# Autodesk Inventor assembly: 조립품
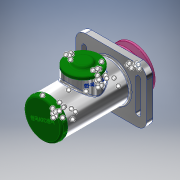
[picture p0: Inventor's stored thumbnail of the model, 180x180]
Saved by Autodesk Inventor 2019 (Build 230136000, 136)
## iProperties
Created: 2021-07
Part Number: 조립품
Material: 일반
Document SubType Name: Assembly
Designer: jun-2-10
Author: jun-2-10
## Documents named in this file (20)
- C:\Users\jun-2-10\Desktop\710706V1017\710706V1017\조립품.iam
- C:\Users\jun-2-10\Desktop\710706V1017\710706V1017\본체.ipt
- C:\Users\jun-2-10\Desktop\710706V1017\710706V1017\사이드 커버.ipt
- 사이드 커버.ipt
- C:\Users\jun-2-10\Desktop\710706V1017\710706V1017\축.ipt
- C:\Users\jun-2-10\Desktop\710706V1017\710706V1017\멈춤링 15 x 1.ipt
- C:\Users\jun-2-10\Desktop\710706V1017\710706V1017\멈춤링 35 x 1.6.ipt
- C:\Users\jun-2-10\Desktop\710706V1017\710706V1017\베어링 15 x 35 x 11.ipt
- C:\Users\jun-2-10\Desktop\710706V1017\710706V1017\부시1.ipt
- C:\Users\jun-2-10\Desktop\710706V1017\710706V1017\부시2.ipt
- C:\Users\jun-2-10\Desktop\710706V1017\710706V1017\와셔 10 x 21.ipt
- C:\Users\jun-2-10\Desktop\710706V1017\710706V1017\너트 M10.ipt
- C:\Users\jun-2-10\Desktop\710706V1017\710706V1017\키 4 x 4 x 18.ipt
- C:\Users\jun-2-10\Desktop\710706V1017\710706V1017\V-벨트풀리.ipt
- C:\Users\jun-2-10\Desktop\710706V1017\710706V1017\와셔 4 x 16.ipt
- C:\Users\jun-2-10\Desktop\710706V1017\710706V1017\볼트 M4 x 10.ipt
- C:\Users\jun-2-10\Desktop\710706V1017\710706V1017\오일 실 15 25 7.ipt
- C:\Users\jun-2-10\Desktop\710706V1017\710706V1017\와셔 3 x 6.ipt
- C:\Users\jun-2-10\Desktop\710706V1017\710706V1017\십자볼트 M3 x 10.ipt
- C:\Users\jun-2-10\Desktop\710706V1017\710706V1017\탑 커버.ipt
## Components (2 placed, 2 different names)
1. V-벨트풀리:1
2. ISO 4017 M4 x 10:1
